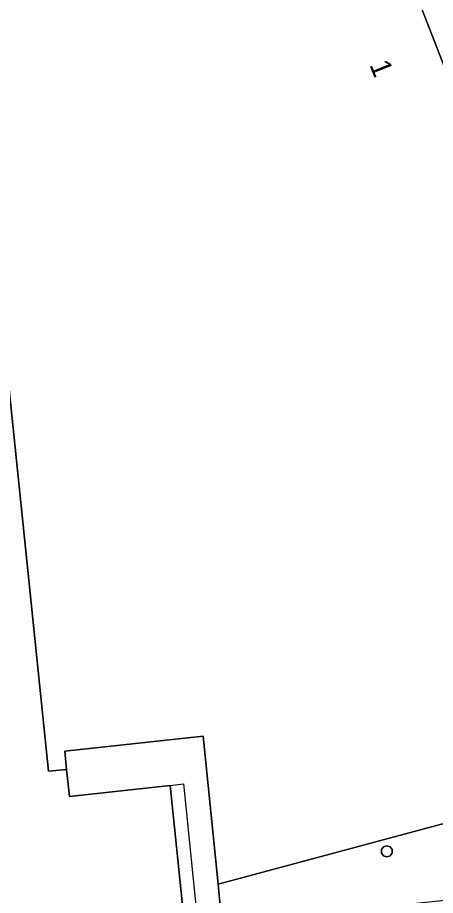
# Model space of a CAD drawing. Extents: x 160675 to 161153, y 383241 to 383714.
# Drawn here: x 161095.4 to 161115.83, y 383592.29 to 383635.2 of the extents above; entities that cross this region are included whole.
import ezdxf

# ---------------------------------------------------------------- set-up
doc = ezdxf.new("R2010")
doc.units = 0
for name, color, linetype in [('IMGEO_Pand', 7, 'Continuous'), ('IMGEO_Pand_nummerreeks', 7, 'Continuous'), ('IMGEO_Pand_overbouw', 7, 'Continuous'), ('IMGEO_Voetpad_open', 7, 'Continuous')]:
    doc.layers.add(name, color=color, linetype=linetype)

msp = doc.modelspace()

# ---------------------------------------------------------------- linework, layer by layer
at = {"layer": 'IMGEO_Pand'}
for points in [[(161126.246, 383601.922), (161127.726, 383601.955), (161127.701, 383603.071), (161127.441, 383604.134), (161125.936, 383607.995), (161124.848, 383610.787), (161109.653, 383649.767), (161104.111, 383663.984), (161093.866, 383662.93), (161090.454, 383662.579), (161090.629, 383660.888), (161090.467, 383660.87), (161096.92, 383598.37), (161097.8, 383598.45), (161097.706, 383599.338), (161104.472, 383600.076), (161105.209, 383592.833), (161124.609, 383598.054), (161124.448, 383598.436)], [(161027.74, 383581.8), (161076.456, 383586.789), (161075.89, 383591.57), (161084.73, 383592.49), (161085.023, 383589.483), (161085.1, 383588.687), (161085.197, 383587.691), (161089.735, 383588.159), (161096.343, 383588.84), (161099.422, 383589.166), (161099.226, 383591.056), (161103.493, 383591.497), (161102.865, 383597.667), (161097.94, 383597.13), (161097.8, 383598.45), (161096.92, 383598.37), (161090.467, 383660.87), (161085.69, 383660.33), (161085.53, 383662.01), (161003.438, 383653.613)]]:
    msp.add_lwpolyline(points, dxfattribs=at)
msp.add_lwpolyline([(161113.611, 383594.22), (161113.711, 383594.358), (161113.711, 383594.528), (161113.611, 383594.665), (161113.45, 383594.718), (161113.288, 383594.665), (161113.188, 383594.528), (161113.188, 383594.358), (161113.288, 383594.22), (161113.45, 383594.168)], close=True, dxfattribs=at)
at = {"layer": 'IMGEO_Pand_overbouw'}
for points in [[(161104.33, 383589.715), (161130.783, 383592.297), (161134.466, 383592.657), (161133.637, 383594.78), (161132.48, 383597.748), (161128.903, 383606.916), (161128.029, 383609.158), (161126.944, 383611.937), (161106.542, 383664.234), (161103.793, 383671.281), (161093.399, 383670.221), (161093.128, 383670.1), (161093.866, 383662.93), (161104.111, 383663.984), (161109.653, 383649.767), (161124.848, 383610.787), (161125.936, 383607.995), (161127.441, 383604.134), (161127.701, 383603.071), (161127.726, 383601.955), (161126.246, 383601.922)], [(161124.448, 383598.436), (161124.609, 383598.054), (161105.209, 383592.833), (161104.472, 383600.076), (161097.706, 383599.338), (161097.8, 383598.45), (161097.94, 383597.13), (161102.865, 383597.667), (161103.516, 383597.748), (161104.33, 383589.715)]]:
    msp.add_lwpolyline(points, dxfattribs=at)
at = {"layer": 'IMGEO_Voetpad_open'}
for points in [[(161114.755, 383641.207), (161111.179, 383650.348), (161111.074, 383650.297), (161109.653, 383649.767), (161124.848, 383610.787), (161125.936, 383607.995), (161127.441, 383604.134), (161127.701, 383603.071), (161127.726, 383601.955), (161126.246, 383601.922)], [(161124.448, 383598.436), (161124.609, 383598.054), (161105.209, 383592.833), (161105.316, 383591.598), (161105.374, 383590.924), (161129.716, 383593.455), (161132.48, 383597.748), (161132.757, 383598.178), (161129.285, 383607.071), (161128.903, 383606.916), (161128.348, 383606.69), (161127.493, 383608.86), (161126.399, 383611.638), (161114.755, 383641.207)]]:
    msp.add_lwpolyline(points, dxfattribs=at)
for points in [[(161104.472, 383600.076), (161097.706, 383599.338), (161097.8, 383598.45), (161097.94, 383597.13), (161102.865, 383597.667), (161103.493, 383591.497), (161105.316, 383591.598), (161105.209, 383592.833)], [(161113.711, 383594.528), (161113.711, 383594.358), (161113.611, 383594.22), (161113.45, 383594.168), (161113.288, 383594.22), (161113.188, 383594.358), (161113.188, 383594.528), (161113.288, 383594.665), (161113.45, 383594.718), (161113.611, 383594.665)]]:
    msp.add_lwpolyline(points, close=True, dxfattribs=at)

# ---------------------------------------------------------------- texts
at = {"layer": 'IMGEO_Pand_nummerreeks'}
msp.add_text('1', height=1, rotation=291.6294, dxfattribs=at).set_placement((161112.594, 383632.895))

doc.saveas('drawing.dxf')
